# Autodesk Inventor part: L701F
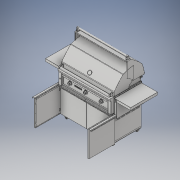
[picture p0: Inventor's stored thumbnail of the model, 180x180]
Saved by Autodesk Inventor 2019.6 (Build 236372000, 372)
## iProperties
Created: 2025-04
Part Number: L701F
Material: Generic
Description: CATIA V5 STEP
Document SubType Name: Modeling
Designer: MMAK
Authority: none
Density: 1 g/cm^3
Appearance: Default
Company: none
Title: C:\Users\MMAK\Documents\SmarTeam\WEBSITE CAD\SEDONA\2025 SEDONA\L701F.stp
Author: none
Revision Number: ANY
Sending System: CATIA V5 STEP AP203 v2
Preprocessor: CATIA Unofficial Packaging Version SP2
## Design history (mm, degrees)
feature "81799-1_81716-1_81715-1_38005-1-solid1"
feature "81799-1_81716-1_81715-1_32769-1-solid1"
feature "81799-1_81716-1_81715-1_32769-2-solid1"
feature "81799-1_81716-1_81715-1_32218-1-solid1"
feature "81799-1_81716-1_81715-1_32218-2-solid1"
feature "81799-1_81716-1_81534-2_37528-2-solid1"
feature "81799-1_81716-1_81534-2_32769-1-solid1"
feature "81799-1_81716-1_81534-2_32769-2-solid1"
feature "81799-1_81716-1_81534-2_32218-14-solid1"
feature "81799-1_81716-1_81534-2_37165-1-solid1"
feature "81799-1_81716-1_81533-2_37528-1-solid1"
feature "81799-1_81716-1_81533-2_32218-5-solid1"
feature "81799-1_81716-1_81533-2_32218-6-solid1"
feature "81799-1_81716-1_81533-2_32218-7-solid1"
feature "81799-1_81716-1_81533-2_32218-9-solid1"
feature "81799-1_81716-1_81533-2_32218-11-solid1"
feature "81799-1_81716-1_81533-2_32769-1-solid1"
feature "81799-1_81716-1_81533-2_32769-2-solid1"
feature "81799-1_81716-1_81533-2_37165-11-solid1"
feature "81799-1_81716-1_81710-1_38004-1-solid1"
feature "81799-1_81716-1_81710-1_38003-1-solid1"
feature "81799-1_81716-1_81710-1_32769-1-solid1"
feature "81799-1_81716-1_81710-1_32769-2-solid1"
feature "81799-1_81716-1_81710-1_32769-3-solid1"
feature "81799-1_81716-1_81710-1_32769-4-solid1"
feature "81799-1_81716-1_81710-1_32769-5-solid1"
feature "81799-1_81716-1_81710-1_32769-6-solid1"
feature "81799-1_81716-1_81710-1_32769-7-solid1"
feature "81799-1_81716-1_81710-1_32769-8-solid1"
feature "81799-1_81716-1_81710-1_32769-9-solid1"
feature "81799-1_81716-1_81710-1_32769-10-solid1"
feature "81799-1_81716-1_81710-1_32769-11-solid1"
feature "81799-1_81716-1_81710-1_32769-12-solid1"
feature "81799-1_81716-1_81710-1_32769-21-solid1"
feature "81799-1_81716-1_81710-1_32769-25-solid1"
feature "81799-1_81716-1_81710-1_32769-26-solid1"
feature "81799-1_81716-1_81710-1_32769-27-solid1"
feature "81799-1_81716-1_30662-1-solid1"
feature "81799-1_81716-1_30662-1-solid2"
feature "81799-1_81716-1_30662-1-solid3"
feature "81799-1_81716-1_33843-1-solid1"
feature "81799-1_81716-1_33843-1-solid2"
feature "81799-1_81716-1_33843-2-solid1"
feature "81799-1_81716-1_33843-2-solid2"
feature "81799-1_81716-1_37167-1-solid1"
feature "81799-1_81716-1_37167-17-solid1"
feature "81799-1_81716-1_37167-18-solid1"
feature "81799-1_81716-1_37167-19-solid1"
feature "81799-1_81716-1_37167-21-solid1"
feature "81799-1_81716-1_37167-24-solid1"
feature "81799-1_81716-1_37167-26-solid1"
feature "81799-1_81716-1_37167-28-solid1"
feature "81799-1_81716-1_37167-30-solid1"
feature "81799-1_81716-1_37167-32-solid1"
feature "81799-1_81716-1_37167-34-solid1"
feature "81799-1_81716-1_37167-36-solid1"
feature "81799-1_81716-1_37167-38-solid1"
feature "81799-1_81716-1_37167-40-solid1"
feature "81799-1_81716-1_37167-42-solid1"
feature "81799-1_81716-1_37167-44-solid1"
feature "81799-1_81716-1_30662-2-solid1"
feature "81799-1_81716-1_30662-2-solid2"
feature "81799-1_81716-1_30662-2-solid3"
feature "81799-1_81404-3_37070-1-solid1"
feature "81799-1_81404-3_32769-1-solid1"
feature "81799-1_81404-3_32769-2-solid1"
feature "81799-1_81404-3_32769-4-solid1"
feature "81799-1_81404-3_32769-6-solid1"
feature "81799-1_37888-1-solid1"
feature "81799-1_38008-1-solid1"
feature "81799-1_37168-1-solid1"
feature "81799-1_37168-4-solid1"
feature "81799-1_70696-2_37100-1-solid1"
feature "81799-1_70696-2_34888-1-solid1"
feature "81799-1_70696-2_31643-1-solid1"
feature "81799-1_70696-2_31643-3-solid1"
feature "81799-1_70696-1_37100-1-solid1"
feature "81799-1_70696-1_34888-1-solid1"
feature "81799-1_70696-1_31643-1-solid1"
feature "81799-1_70696-1_31643-3-solid1"
feature "81799-1_70696-3_37100-1-solid1"
feature "81799-1_70696-3_31643-2-solid1"
feature "81799-1_70696-3_34888-3-solid1"
feature "81799-1_70696-3_31643-4-solid1"
feature "81799-1_70696-4_37100-1-solid1"
feature "81799-1_70696-4_31643-2-solid1"
feature "81799-1_70696-4_34888-3-solid1"
feature "81799-1_70696-4_31643-4-solid1"
feature "81799-1_31876-10-solid1"
feature "81799-1_31876-1-solid1"
feature "81799-1_31876-2-solid1"
feature "81799-1_31876-5-solid1"
feature "81799-1_31876-11-solid1"
feature "81799-1_31876-12-solid1"
feature "81799-1_37167-47-solid1"
feature "81799-1_37167-45-solid1"
feature "81799-1_37167-48-solid1"
feature "81799-1_37167-46-solid1"
feature "81799-1_37167-41-solid1"
feature "81799-1_37167-43-solid1"
feature "81799-1_37167-49-solid1"
feature "81799-1_37167-50-solid1"
feature "81799-1_37165-3-solid1"
feature "81799-1_37165-2-solid1"
feature "81799-1_30292-1-solid1"
feature "81799-1_30292-2-solid1"
feature "81799-1_30292-4-solid1"
feature "81799-1_30292-6-solid1"
feature "81799-1_81530-1_37102-1-solid1"
feature "81799-1_81530-1_31205-1-solid1"
feature "81799-1_81530-1_31206-5-solid1"
feature "81799-1_81530-1_31206-6-solid1"
feature "81799-1_81530-1_31206-4-solid1"
feature "81799-1_81530-1_31206-7-solid1"
feature "81799-1_37166-6-solid1"
feature "81799-1_37166-10-solid1"
feature "81799-1_37166-12-solid1"
feature "81799-1_37166-15-solid1"
feature "81799-1_37795-1-solid1"
feature "81799-1_37795-2-solid1"
feature "81799-1_37795-3-solid1"
feature "81799-1_37795-4-solid1"
feature "81799-1_81790-1_81794-1_37540-1-solid1"
feature "81799-1_81790-1_81794-1_38154-1-solid1"
feature "81799-1_81790-1_81794-1_37797-1-solid1"
feature "81799-1_81790-1_81794-1_30292-1-solid1"
feature "81799-1_81790-1_81794-1_30292-2-solid1"
feature "81799-1_81790-1_81794-1_30292-3-solid1"
feature "81799-1_81790-1_81794-1_30292-5-solid1"
feature "81799-1_81790-1_81794-1_30292-6-solid1"
feature "81799-1_81790-1_81794-1_30292-7-solid1"
feature "81799-1_81790-1_81794-1_30292-8-solid1"
feature "81799-1_81790-1_81794-1_30292-9-solid1"
feature "81799-1_81790-1_81794-1_30292-10-solid1"
feature "81799-1_81790-1_81794-1_30292-11-solid1"
feature "81799-1_81790-1_81794-1_30292-12-solid1"
feature "81799-1_81790-1_81794-1_30292-13-solid1"
feature "81799-1_81790-1_81794-1_30292-14-solid1"
feature "81799-1_81790-1_81794-1_30292-16-solid1"
feature "81799-1_81790-1_81794-1_30292-18-solid1"
feature "81799-1_81790-1_81794-1_30292-20-solid1"
feature "81799-1_81790-1_81794-1_30292-22-solid1"
feature "81799-1_81790-1_32218-1-solid1"
feature "81799-1_81790-1_32218-2-solid1"
feature "81799-1_81790-1_32218-3-solid1"
feature "81799-1_81790-1_32218-4-solid1"
feature "81799-1_81790-2_81794-1_37540-1-solid1"
feature "81799-1_81790-2_81794-1_38154-1-solid1"
feature "81799-1_81790-2_81794-1_37797-1-solid1"
feature "81799-1_81790-2_81794-1_30292-1-solid1"
feature "81799-1_81790-2_81794-1_30292-2-solid1"
feature "81799-1_81790-2_81794-1_30292-3-solid1"
feature "81799-1_81790-2_81794-1_30292-5-solid1"
feature "81799-1_81790-2_81794-1_30292-6-solid1"
feature "81799-1_81790-2_81794-1_30292-7-solid1"
feature "81799-1_81790-2_81794-1_30292-8-solid1"
feature "81799-1_81790-2_81794-1_30292-9-solid1"
feature "81799-1_81790-2_81794-1_30292-10-solid1"
feature "81799-1_81790-2_81794-1_30292-11-solid1"
feature "81799-1_81790-2_81794-1_30292-12-solid1"
feature "81799-1_81790-2_81794-1_30292-13-solid1"
feature "81799-1_81790-2_81794-1_30292-14-solid1"
feature "81799-1_81790-2_81794-1_30292-16-solid1"
feature "81799-1_81790-2_81794-1_30292-18-solid1"
feature "81799-1_81790-2_81794-1_30292-20-solid1"
feature "81799-1_81790-2_81794-1_30292-22-solid1"
feature "81799-1_81790-2_32218-1-solid1"
feature "81799-1_81790-2_32218-2-solid1"
feature "81799-1_81790-2_32218-3-solid1"
feature "81799-1_81790-2_32218-4-solid1"
feature "81799-1_81791-1_81795-1_37540-1-solid1"
feature "81799-1_81791-1_81795-1_37549-1-solid1"
feature "81799-1_81791-1_81795-1_38154-1-solid1"
feature "81799-1_81791-1_81795-1_30292-1-solid1"
feature "81799-1_81791-1_81795-1_30292-2-solid1"
feature "81799-1_81791-1_81795-1_30292-3-solid1"
feature "81799-1_81791-1_81795-1_30292-4-solid1"
feature "81799-1_81791-1_81795-1_30292-5-solid1"
feature "81799-1_81791-1_81795-1_30292-6-solid1"
feature "81799-1_81791-1_81795-1_30292-7-solid1"
feature "81799-1_81791-1_81795-1_30292-8-solid1"
feature "81799-1_81791-1_81795-1_30292-9-solid1"
feature "81799-1_81791-1_81795-1_30292-10-solid1"
feature "81799-1_81791-1_81795-1_30292-11-solid1"
feature "81799-1_81791-1_81795-1_30292-12-solid1"
feature "81799-1_81791-1_81795-1_30292-13-solid1"
feature "81799-1_81791-1_81795-1_30292-15-solid1"
feature "81799-1_81791-1_81795-1_30292-17-solid1"
feature "81799-1_81791-1_81795-1_30292-19-solid1"
feature "81799-1_81791-1_81795-1_30292-21-solid1"
feature "81799-1_81791-1_32218-1-solid1"
feature "81799-1_81791-1_32218-2-solid1"
feature "81799-1_81791-1_32218-3-solid1"
feature "81799-1_81791-1_32218-4-solid1"
feature "81799-1_81791-2_81795-1_37540-1-solid1"
feature "81799-1_81791-2_81795-1_37549-1-solid1"
feature "81799-1_81791-2_81795-1_38154-1-solid1"
feature "81799-1_81791-2_81795-1_30292-1-solid1"
feature "81799-1_81791-2_81795-1_30292-2-solid1"
feature "81799-1_81791-2_81795-1_30292-3-solid1"
feature "81799-1_81791-2_81795-1_30292-4-solid1"
feature "81799-1_81791-2_81795-1_30292-5-solid1"
feature "81799-1_81791-2_81795-1_30292-6-solid1"
feature "81799-1_81791-2_81795-1_30292-7-solid1"
feature "81799-1_81791-2_81795-1_30292-8-solid1"
feature "81799-1_81791-2_81795-1_30292-9-solid1"
feature "81799-1_81791-2_81795-1_30292-10-solid1"
feature "81799-1_81791-2_81795-1_30292-11-solid1"
feature "81799-1_81791-2_81795-1_30292-12-solid1"
feature "81799-1_81791-2_81795-1_30292-13-solid1"
feature "81799-1_81791-2_81795-1_30292-15-solid1"
feature "81799-1_81791-2_81795-1_30292-17-solid1"
feature "81799-1_81791-2_81795-1_30292-19-solid1"
feature "81799-1_81791-2_81795-1_30292-21-solid1"
feature "81799-1_81791-2_32218-1-solid1"
feature "81799-1_81791-2_32218-2-solid1"
feature "81799-1_81791-2_32218-3-solid1"
feature "81799-1_81791-2_32218-4-solid1"
feature "L701-1_80780-1_34565-2-solid1"
feature "L701-1_80780-1_34563-2-solid1"
feature "L701-1_80780-1_34564-2-solid1"
feature "L701-1_80780-1_31643-1-solid1"
feature "L701-1_80780-1_31643-2-solid1"
feature "L701-1_80780-1_30616-3-solid1"
feature "L701-1_80780-1_30616-4-solid1"
feature "L701-1_80780-1_30616-5-solid1"
feature "L701-1_80780-1_30616-6-solid1"
feature "L701-1_80780-1_30616-9-solid1"
feature "L701-1_80780-1_30616-10-solid1"
feature "L701-1_80780-1_30616-11-solid1"
feature "L701-1_80780-1_30616-12-solid1"
feature "L701-1_80780-1_33759-1-solid1"
feature "L701-1_80780-1_33758-1-solid1"
feature "L701-1_80780-1_30292-1-solid1"
feature "L701-1_80780-1_30292-2-solid1"
feature "L701-1_80780-1_14011-1-solid1"
feature "L701-1_80780-1_14011-2-solid1"
feature "L701-1_80780-1_14011-3-solid1"
feature "L701-1_80780-1_14011-4-solid1"
feature "L701-1_80780-1_14011-5-solid1"
feature "L701-1_80780-1_14011-6-solid1"
feature "L701-1_80780-1_30616-16-solid1"
feature "L701-1_80780-1_30616-17-solid1"
feature "L701-1_80780-1_30616-13-solid1"
feature "L701-1_80780-1_30616-14-solid1"
feature "L701-1_80780-1_30616-15-solid1"
feature "L701-1_80780-1_34566-3-solid1"
feature "L701-1_80780-1_14034-1-solid1"
feature "L701-1_80780-1_14034-2-solid1"
feature "L701-1_80780-1_14034-3-solid1"
feature "L701-1_80780-1_14034-4-solid1"
feature "L701-1_80780-1_14034-5-solid1"
feature "L701-1_80780-1_14011-7-solid1"
feature "L701-1_80780-1_14011-8-solid1"
feature "L701-1_80780-1_14011-9-solid1"
feature "L701-1_80780-1_14011-11-solid1"
feature "L701-1_80780-1_14011-12-solid1"
feature "L701-1_80780-1_14011-14-solid1"
feature "L701-1_80780-1_14011-15-solid1"
feature "L701-1_80780-1_14011-17-solid1"
feature "L701-1_80780-1_14011-18-solid1"
feature "L701-1_80780-1_14011-20-solid1"
feature "L701-1_80780-1_14011-22-solid1"
feature "L701-1_80780-1_14011-24-solid1"
feature "L701-1_80780-1_14011-26-solid1"
feature "L701-1_80780-1_14011-28-solid1"
feature "L701-1_80780-1_14011-31-solid1"
feature "L701-1_80780-1_14011-35-solid1"
feature "L701-1_80780-1_14011-37-solid1"
feature "L701-1_80780-1_14011-39-solid1"
feature "L701-1_80780-1_14011-41-solid1"
feature "L701-1_80780-1_32620-1-solid1"
feature "L701-1_80780-1_32620-2-solid1"
feature "L701-1_80780-1_32620-3-solid1"
feature "L701-1_80780-1_32620-4-solid1"
feature "L701-1_80780-1_32620-5-solid1"
feature "L701-1_80780-1_32620-6-solid1"
feature "L701-1_80780-1_14011-43-solid1"
feature "L701-1_80780-1_14011-45-solid1"
feature "L701-1_70835-1_33767-1-solid1"
feature "L701-1_70835-1_33768-1-solid1"
feature "L701-1_70835-1_34572-1-solid1"
feature "L701-1_70835-2_33767-1-solid1"
feature "L701-1_70835-2_33768-1-solid1"
feature "L701-1_70835-2_34572-1-solid1"
feature "L701-1_81797-1_70833-1_L18041-1-solid1"
feature "L701-1_81797-1_70833-1_33763-1-solid1"
feature "L701-1_81797-1_70833-1_37975-1-solid1"
feature "L701-1_81797-1_32218-1-solid1"
feature "L701-1_81797-1_32218-2-solid1"
feature "L701-1_81705-1_70816-1_37995-1-solid1"
feature "L701-1_81705-1_70816-1_14011-1-solid1"
feature "L701-1_81705-1_81628-1_37837-2-solid1"
feature "L701-1_81705-1_81628-1_32218-3-solid1"
feature "L701-1_81705-1_81628-1_32218-4-solid1"
feature "L701-1_81705-1_81628-1_31782-1-solid1"
feature "L701-1_81705-1_81628-1_32769-1-solid1"
feature "L701-1_81705-1_81628-1_32769-2-solid1"
feature "L701-1_81705-1_81628-1_32769-3-solid1"
feature "L701-1_81705-1_81628-1_32769-4-solid1"
feature "L701-1_81705-1_81627-1_37834-2-solid1"
feature "L701-1_81705-1_81627-1_32769-1-solid1"
feature "L701-1_81705-1_81627-1_32769-2-solid1"
feature "L701-1_81705-1_81627-1_32769-3-solid1"
feature "L701-1_81705-1_81627-1_32769-4-solid1"
feature "L701-1_81705-1_81627-1_32769-5-solid1"
feature "L701-1_81705-1_81627-1_31782-1-solid1"
feature "L701-1_81705-1_81627-1_32218-3-solid1"
feature "L701-1_81705-1_81627-1_32218-4-solid1"
feature "L701-1_81705-1_37845-1-solid1"
feature "L701-1_81705-1_37846-1-solid1"
feature "L701-1_81705-1_32470-1-solid1"
feature "L701-1_81705-1_32470-2-solid1"
feature "L701-1_81705-1_14012-1-solid1"
feature "L701-1_81705-1_14012-2-solid1"
feature "L701-1_81705-1_14012-4-solid1"
feature "L701-1_81705-1_14012-6-solid1"
feature "L701-1_81705-1_14012-8-solid1"
feature "L701-1_81705-1_14012-10-solid1"
feature "L701-1_81705-1_14012-12-solid1"
feature "L701-1_81705-1_14012-14-solid1"
feature "L701-1_81705-1_14014-1-solid1"
feature "L701-1_81705-1_14014-2-solid1"
feature "L701-1_81705-1_14014-4-solid1"
feature "L701-1_81705-1_14014-6-solid1"
feature "L701-1_38164-1-solid1"
feature "L701-1_80787-1_80785-1_34603-1-solid1"
feature "L701-1_80787-1_80785-1_34603-1-solid2"
feature "L701-1_80787-1_80785-1_L10041-1-solid1"
feature "L701-1_80787-1_80785-1_L10041-2-solid1"
feature "L701-1_80787-1_13029-1-solid1"
feature "L701-1_80787-1_34267-1-solid1"
feature "L701-1_80787-1_34268-1-solid1"
feature "L701-1_80787-1_13024-1-solid1"
feature "NONE"
feature "NONE:1"
feature "NONE:2"
feature "L701-1_80787-1_13024-2-solid1"
feature "L701-1_33558-1-solid1"
feature "L701-1_10001-1-solid1"
feature "L701-1_10001-2-solid1"
feature "L701-1_10001-3-solid1"
feature "L701-1_31773-1-solid1"
feature "L701-1_31773-2-solid1"
feature "L701-1_31773-3-solid1"
feature "L701-1_81630-1_32106-1-solid1"
feature "L701-1_81630-1_Part2^81630-1-solid1"
feature "L701-1_81630-1_Part2^81630-1-solid2"
feature "L701-1_11117-1-solid1"
feature "L701-1_11117-2-solid1"
feature "L701-1_11117-3-solid1"
feature "L701-1_11117-4-solid1"
feature "L701-1_L20016-1-solid1"
feature "L701-1_L20016-2-solid1"
feature "L701-1_L20016-3-solid1"
feature "L701-1_L20016-4-solid1"
feature "L701-1_34605-1-solid1"
feature "L701-1_34605-2-solid1"
feature "L701-1_30417-1-solid1"
feature "L701-1_34106-1-solid1"
feature "L701-1_14013-1-solid1"
feature "L701-1_14013-2-solid1"
feature "L701-1_36967-1-solid1"
feature "L701-1_36967-2-solid1"
feature "L701-1_14012-1-solid1"
feature "L701-1_14012-2-solid1"
feature "L701-1_14012-3-solid1"
feature "L701-1_14012-4-solid1"
feature "L701-1_14012-5-solid1"
feature "L701-1_32477-1-solid1"
feature "L701-1_32477-2-solid1"
feature "L701-1_38157-1-solid1"
feature "L701-1_38158-1-solid1"
feature "L701-1_31930-1-solid1"
feature "L701-1_31930-3-solid1"
feature "L701-1_31930-4-solid1"
feature "L701-1_31930-5-solid1"
feature "L701-1_31930-6-solid1"
feature "L701-1_31930-7-solid1"
feature "L701-1_31930-8-solid1"
feature "L701-1_31930-9-solid1"
feature "L701-1_31930-10-solid1"
feature "L701-1_32554-1-solid1"
feature "L701-1_32554-1-solid2"
feature "L701-1_32554-2-solid1"
feature "L701-1_32554-2-solid2"
feature "L701-1_32554-3-solid1"
feature "L701-1_32554-3-solid2"
body "Solid1"
body "Solid2"
body "Solid3"
body "Solid4"
body "Solid5"
body "Solid6"
body "Solid7"
body "Solid8"
body "Solid9"
body "Solid10"
body "Solid11"
body "Solid12"
body "Solid13"
body "Solid14"
body "Solid15"
body "Solid16"
body "Solid17"
body "Solid18"
body "Solid19"
body "Solid20"
body "Solid21"
body "Solid22"
body "Solid23"
body "Solid24"
body "Solid25"
body "Solid26"
body "Solid27"
body "Solid28"
body "Solid29"
body "Solid30"
body "Solid31"
body "Solid32"
body "Solid33"
body "Solid34"
body "Solid35"
body "Solid36"
body "Solid37"
body "Solid38"
body "Solid39"
body "Solid40"
body "Solid41"
body "Solid42"
body "Solid43"
body "Solid44"
body "Solid45"
body "Solid46"
body "Solid47"
body "Solid48"
body "Solid49"
body "Solid50"
body "Solid51"
body "Solid52"
body "Solid53"
body "Solid54"
body "Solid55"
body "Solid56"
body "Solid57"
body "Solid58"
body "Solid59"
body "Solid60"
body "Solid61"
body "Solid62"
body "Solid63"
body "Solid64"
body "Solid65"
body "Solid66"
body "Solid67"
body "Solid68"
body "Solid69"
body "Solid70"
body "Solid71"
body "Solid72"
body "Solid73"
body "Solid74"
body "Solid75"
body "Solid76"
body "Solid77"
body "Solid78"
body "Solid79"
body "Solid80"
body "Solid81"
body "Solid82"
body "Solid83"
body "Solid84"
body "Solid85"
body "Solid86"
body "Solid87"
body "Solid88"
body "Solid89"
body "Solid90"
body "Solid91"
body "Solid92"
body "Solid93"
body "Solid94"
body "Solid95"
body "Solid96"
body "Solid97"
body "Solid98"
body "Solid99"
body "Solid100"
body "Solid101"
body "Solid102"
body "Solid103"
body "Solid104"
body "Solid105"
body "Solid106"
body "Solid107"
body "Solid108"
body "Solid109"
body "Solid110"
body "Solid111"
body "Solid112"
body "Solid113"
body "Solid114"
body "Solid115"
body "Solid116"
body "Solid117"
body "Solid118"
body "Solid119"
body "Solid120"
body "Solid121"
body "Solid122"
body "Solid123"
body "Solid124"
body "Solid125"
body "Solid126"
body "Solid127"
body "Solid128"
body "Solid129"
body "Solid130"
body "Solid131"
body "Solid132"
body "Solid133"
body "Solid134"
body "Solid135"
body "Solid136"
body "Solid137"
body "Solid138"
body "Solid139"
body "Solid140"
body "Solid141"
body "Solid142"
body "Solid143"
body "Solid144"
body "Solid145"
body "Solid146"
body "Solid147"
body "Solid148"
body "Solid149"
body "Solid150"
body "Solid151"
body "Solid152"
body "Solid153"
body "Solid154"
body "Solid155"
body "Solid156"
body "Solid157"
body "Solid158"
body "Solid159"
body "Solid160"
body "Solid161"
body "Solid162"
body "Solid163"
body "Solid164"
body "Solid165"
body "Solid166"
body "Solid167"
body "Solid168"
body "Solid169"
body "Solid170"
body "Solid171"
body "Solid172"
body "Solid173"
body "Solid174"
body "Solid175"
body "Solid176"
body "Solid177"
body "Solid178"
body "Solid179"
body "Solid180"
body "Solid181"
body "Solid182"
body "Solid183"
body "Solid184"
body "Solid185"
body "Solid186"
body "Solid187"
body "Solid188"
body "Solid189"
body "Solid190"
body "Solid191"
body "Solid192"
body "Solid193"
body "Solid194"
body "Solid195"
body "Solid196"
body "Solid197"
body "Solid198"
body "Solid199"
body "Solid200"
body "Solid201"
body "Solid202"
body "Solid203"
body "Solid204"
body "Solid205"
body "Solid206"
body "Solid207"
body "Solid208"
body "Solid209"
body "Solid210"
body "Solid211"
body "Solid212"
body "Solid213"
body "Solid214"
body "Solid215"
body "Solid216"
body "Solid217"
body "Solid218"
body "Solid219"
body "Solid220"
body "Solid221"
body "Solid222"
body "Solid223"
body "Solid224"
body "Solid225"
body "Solid226"
body "Solid227"
body "Solid228"
body "Solid229"
body "Solid230"
body "Solid231"
body "Solid232"
body "Solid233"
body "Solid234"
body "Solid235"
body "Solid236"
body "Solid237"
body "Solid238"
body "Solid239"
body "Solid240"
body "Solid241"
body "Solid242"
body "Solid243"
body "Solid244"
body "Solid245"
body "Solid246"
body "Solid247"
body "Solid248"
body "Solid249"
body "Solid250"
body "Solid251"
body "Solid252"
body "Solid253"
body "Solid254"
body "Solid255"
body "Solid256"
body "Solid257"
body "Solid258"
body "Solid259"
body "Solid260"
body "Solid261"
body "Solid262"
body "Solid263"
body "Solid264"
body "Solid265"
body "Solid266"
body "Solid267"
body "Solid268"
body "Solid269"
body "Solid270"
body "Solid271"
body "Solid272"
body "Solid273"
body "Solid274"
body "Solid275"
body "Solid276"
body "Solid277"
body "Solid278"
body "Solid279"
body "Solid280"
body "Solid281"
body "Solid282"
body "Solid283"
body "Solid284"
body "Solid285"
body "Solid286"
body "Solid287"
body "Solid288"
body "Solid289"
body "Solid290"
body "Solid291"
body "Solid292"
body "Solid293"
body "Solid294"
body "Solid295"
body "Solid296"
body "Solid297"
body "Solid298"
body "Solid299"
body "Solid300"
body "Solid301"
body "Solid302"
body "Solid303"
body "Solid304"
body "Solid305"
body "Solid306"
body "Solid307"
body "Solid308"
body "Solid309"
body "Solid310"
body "Solid311"
body "Solid312"
body "Solid313"
body "Solid314"
body "Solid315"
body "Solid316"
body "Solid317"
body "Solid318"
body "Solid319"
body "Solid320"
body "Solid321"
body "Solid322"
body "Solid323"
body "Solid324"
body "Solid325"
body "Solid326"
body "Solid327"
body "Solid328"
body "Solid329"
body "Solid330"
body "Solid331"
body "Solid332"
body "Solid333"
body "Solid334"
body "Solid335"
body "Solid336"
body "Solid337"
body "Solid338"
body "Solid339"
body "Solid340"
body "Solid341"
body "Solid342"
body "Solid343"
body "Solid344"
body "Solid345"
body "Solid346"
body "Solid347"
body "Solid348"
body "Solid349"
body "Solid350"
body "Solid351"
body "Solid352"
body "Solid353"
body "Solid354"
body "Solid355"
body "Solid356"
body "Solid357"
body "Solid358"
body "Solid359"
body "Solid360"
body "Solid361"
body "Solid362"
body "Solid363"
body "Solid364"
body "Solid365"
body "Solid366"
body "Solid367"
body "Solid368"
body "Solid369"
body "Solid370"
body "Solid371"
body "Solid372"
body "Solid373"
body "Solid374"
body "Solid375"
body "Solid376"
body "Solid377"
body "Solid378"
body "Solid379"
body "Solid380"
body "Solid381"
body "Solid382"
body "Solid383"
body "Solid384"
body "Solid385"
body "Solid386"
body "Solid387"
body "Solid388"
body "Solid389"
body "Solid390"
body "Solid391"
body "Solid392"
body "Solid393"
body "Solid394"
body "Solid395"
body "Solid396"
body "Solid397"
body "Solid398"
body "Solid399"
body "Solid400"
